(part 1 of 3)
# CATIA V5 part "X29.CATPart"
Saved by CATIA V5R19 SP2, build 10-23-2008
Part number: X-29
Material "Bronze": density 8860 kg/m3, Young's modulus 1.1e+11 Pa, Poisson ratio 0.341, thermal expansion 1.78e-05 1/K
Material "Bronze": density 8860 kg/m3, Young's modulus 1.1e+11 Pa, Poisson ratio 0.341, thermal expansion 1.78e-05 1/K
Material "White": density 7860 kg/m3, Young's modulus 2e+11 Pa, Poisson ratio 0.266
Material "White": density 7860 kg/m3, Young's modulus 2e+11 Pa, Poisson ratio 0.266
Bounding box of the stored display mesh (mm): x -1455.5 to 274.22, y -414.245 to 414.245, z -32.245 to 318.784
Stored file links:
  C:\Users\Pablo\Desktop\Cati XPM\X 29\X29.CATPart
  C:\Program Files\CATIA V19\intel_a\startup\materials\Catalog.CATMaterial
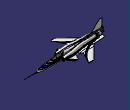
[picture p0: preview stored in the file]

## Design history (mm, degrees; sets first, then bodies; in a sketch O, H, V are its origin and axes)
Set1
  Sketch1 "SIZE CALIBRATE 1 IN 10" on xy-plane, origin (0, 0, 0), H (1, 0, 0), V (0, 1, 0)
    line L1 (-281.9, -45.8) -> (18.1, -45.8)
    point P2 (18.1, -45.8)
    line L2 (-41.1, -46) -> (18.1, -46)
    length L1 = 300
    length L2 = 59.2
    horizontal: L1 H, L2 H
    fix: P2
  Sketch2 "CALIB2" on xy-plane, origin (0, 0, 0), H (1, 0, 0), V (0, 1, 0)
    line L1 (-816.9, 412.5) -> (-816.9, -414.5)
    length L1 = 827
    vertical: L1 V
  Sketch3 "CALIB3" on yz-plane, origin (0, 0, 0), H (0, 1, 0), V (0, 0, 1)
    line L1 (-473.1, 37.9) -> (465.3, 37.9)
    point P2 (465.3, 37.9)
    projected line E1 (412.5, 0) -> (-414.5, 0) from Sketch2.L1
    length L1 = 938.4
    length E1 = 827 (reference)
    horizontal: L1 H
    fix: P2
  Sketch4 on zx-plane, origin (0, 0, 0), H (-1, 0, 0), V (0, 0, 1)
    line L1 (0, 0) -> (267.3, 0)
    line L2 (267.3, 0) -> (267.3, 23.6274)
    length L1 = 267.3
    horizontal: L1 H
    vertical: L2 V
  Sketch5 on xy-plane, origin (0, 0, 0), H (1, 0, 0), V (0, 1, 0)
    line L1 (0, 0) -> (-1457.6, 0)
    length L1 = 1457.6
    horizontal: L1 H
  St3DCurveFeature1 "CATSt3DCurveFeatureName": Order 6, CreationType 2, ClosureMode false, ConstructionPoints ({point type Coord, X -1.9383, Y 5.9343, Z 0}; {point type Coord, X -24.2902, Y 15.8221, Z 0}; {point type Coord, X -62.5655, Y 28.9818, Z 0}; {point type Coord, X -118.7401, Y 40.764, Z 0}; {point type Coord, X -165.694, Y 45.9382, Z 0}; {point type Coord, X -206.5921, Y 48.6971, Z 0}; {point type Coord, X -259.8651, Y 50.5364, Z 0}; {point type Coord, X -315.1978, Y 50.8218, Z 0}; {point type Coord, X -357.1922, Y 50.4817, Z 0}; {point type Coord, X -448.0335, Y 49.8551, Z 0}; {point type Coord, X -538.2728, Y 48.6416, Z 0}; {point type Coord, X -621.671, Y 48.6264, Z 0}; {point type Coord, X -667.4203, Y 47.391, Z 0}; {point type Coord, X -684.8796, Y 46.6781, Z 0}; {point type Coord, X -722.2255, Y 43.9186, Z 0}; {point type Coord, X -762.4405, Y 39.603, Z 0}; {point type Coord, X -787.4084, Y 36.6575, Z 0}; {point type Coord, X -818.1768, Y 33.1426, Z 0}), SymmetryMode false
  St3DCurveFeature2 "CATSt3DCurveFeatureName": Order 6, CreationType 2, ClosureMode false, ConstructionPoints ({point type Coord, X -507.4834, Y 97.0494, Z 0}; {point type Coord, X -530.8481, Y 96.9821, Z 0}; {point type Coord, X -587.9066, Y 97.5878, Z -3.7019}; {point type Coord, X -647.6501, Y 98.1847, Z -9.8719}; {point type Coord, X -697.045, Y 95.7458, Z -18.0162}; {point type Coord, X -747.9643, Y 90.6206, Z -22.9521}; {point type Coord, X -774.7582, Y 85.9469, Z -23.4457}; {point type Coord, X -803.8511, Y 81.6498, Z -24.4677}; {point type Coord, X -823.754, Y 77.7619, Z -24.6797}; {point type Coord, X -849.4023, Y 73.0846, Z -24.6424}; {point type Coord, X -882.7974, Y 68.7832, Z -24.5746}; {point type Coord, X -942.1395, Y 64.0162, Z -24.58}; {point type Coord, X -1018.7672, Y 60.7338, Z -19.3219}; {point type Coord, X -1067.7792, Y 58.296, Z -14.7664}; {point type Coord, X -1138.3186, Y 55.0309, Z -8.0901}; {point type Coord, X -1205.3285, Y 52.1589, Z -2.5716}; {point type Coord, X -1313.7551, Y 46.8707, Z 7.2925}), SymmetryMode false
  St3DCurveFeature3 "CATSt3DCurveFeatureName": Order 6, CreationType 2, ClosureMode false, ConstructionPoints ({point type Coord, X -525.9838, Y 55.3979, Z 0}; {point type Coord, X -543.2538, Y 55.9968, Z 0}; {point type Coord, X -574.5548, Y 56.772, Z 0}; {point type Coord, X -628.0893, Y 57.7, Z 0}; {point type Coord, X -661.1129, Y 56.9586, Z 0}; {point type Coord, X -721.9703, Y 52.2509, Z 0}; {point type Coord, X -755.0441, Y 48.0325, Z 0}; {point type Coord, X -785.2518, Y 44.2786, Z 0}; {point type Coord, X -818.4777, Y 38.7854, Z 0}), SymmetryMode false
  St3DCurveFeature4 "CATSt3DCurveFeatureName": Order 6, CreationType 2, ClosureMode false, ConstructionPoints ({point type OnCurve, Support St3DCurveFeature5, Real 0.228358}; {point type Coord, X -314.3415, Y 1.8332, Z 75.4181}; {point type Coord, X -316.8842, Y 7.3821, Z 75.2006}; {point type Coord, X -319.6261, Y 11.0741, Z 74.9841}; {point type Coord, X -323.9821, Y 15.3852, Z 74.6245}; {point type Coord, X -327.4218, Y 18.0789, Z 74.3128}; {point type Coord, X -331.264, Y 20.7701, Z 73.9983}; {point type Coord, X -336.765, Y 24.0359, Z 73.5381}; {point type Coord, X -343.657, Y 27.3619, Z 72.9256}; {point type Coord, X -355.1724, Y 31.6887, Z 72.4729}; {point type Coord, X -370.8877, Y 36.3523, Z 72.1927}; {point type Coord, X -383.7912, Y 38.4954, Z 72.1897}; {point type Coord, X -397.3184, Y 39.8515, Z 72.0898}; {point type Coord, X -410.2175, Y 40.3042, Z 72.0663}; {point type Coord, X -425.4017, Y 40.2956, Z 71.9107}; {point type Coord, X -445.88, Y 40.0632, Z 72.8633}; {point type Coord, X -475.1823, Y 39.9786, Z 73.1473}; {point type Coord, X -502.6331, Y 40.1639, Z 74.0639}; {point type Coord, X -535.3124, Y 39.986, Z 75.7138}; {point type Coord, X -568.9066, Y 40.0706, Z 80.0391}; {point type Coord, X -609.7247, Y 39.4157, Z 85.4714}; {point type Coord, X -649.066, Y 38.9447, Z 89.9952}; {point type Coord, X -688.7982, Y 37.2164, Z 93.6057}; {point type Coord, X -718.2576, Y 35.6931, Z 96.5137}; {point type Coord, X -745.7382, Y 33.8178, Z 98.8225}; {point type Coord, X -777.5668, Y 30.4924, Z 101.3612}; {point type Coord, X -811.1523, Y 27.5214, Z 104.1194}; {point type Coord, X -849.8104, Y 23.8172, Z 106.5843}; {point type Coord, X -883.9333, Y 20.3055, Z 108.4864}; {point type Coord, X -923.3079, Y 16.9587, Z 111.2445}; {point type Coord, X -963.1815, Y 14.1496, Z 113.0833}; {point type Coord, X -989.4026, Y 11.559, Z 113.0833}), SymmetryMode false
  St3DCurveFeature5 "TOP KINGPOST": Order 6, CreationType 2, ClosureMode false, ConstructionPoints ({point type Coord, X -1.3908, Y 0, Z 4.8279}; {point type Coord, X -8.4225, Y 0, Z 8.3879}; {point type Coord, X -18.6736, Y 0, Z 12.2022}; {point type Coord, X -36.3801, Y 0, Z 17.6269}; {point type Coord, X -51.7991, Y 0, Z 21.9498}; {point type Coord, X -79.871, Y 0, Z 28.6853}; {point type Coord, X -121.7227, Y 0, Z 37.5338}; {point type Coord, X -165.4722, Y 0, Z 46.0493}; {point type Coord, X -214.3044, Y 0, Z 55.3335}; {point type Coord, X -249.384, Y 0, Z 62.278}; {point type Coord, X -279.7975, Y 0, Z 68.5356}; {point type Coord, X -300.5133, Y 0, Z 72.3905}; {point type Coord, X -307.3014, Y 0, Z 73.7945}; {point type Coord, X -311.8016, Y 0, Z 74.8572}; {point type Coord, X -319.3684, Y 0, Z 77.0991}; {point type Coord, X -326.8112, Y 0, Z 79.8683}; {point type Coord, X -345.5423, Y 0, Z 87.9274}; {point type Coord, X -373.9217, Y 0, Z 99.7273}; {point type Coord, X -398.4795, Y 0, Z 110.3991}; {point type Coord, X -427.8123, Y 0, Z 119.7208}; {point type Coord, X -447.7116, Y 0, Z 123.739}; {point type Coord, X -479.5777, Y 0, Z 126.928}; {point type Coord, X -505.6023, Y 0, Z 127.7406}; {point type Coord, X -529.4686, Y 0, Z 127.207}; {point type Coord, X -566.5783, Y 0, Z 124.5391}; {point type Coord, X -585.378, Y 0, Z 122.4048}; {point type Coord, X -609.813, Y 0, Z 120.445}; {point type Coord, X -632.0792, Y 0, Z 119.1111}; {point type Coord, X -659.1454, Y 0, Z 118.4441}; {point type Coord, X -695.947, Y 0, Z 117.5944}; {point type Coord, X -729.46, Y 0, Z 116.9379}; {point type Coord, X -761.9421, Y 0, Z 116.2814}; {point type Coord, X -806.6111, Y 0, Z 115.2966}; {point type Coord, X -849.2643, Y 0, Z 115.4607}; {point type Coord, X -918.1919, Y 0, Z 115.2966}; {point type Coord, X -957.8922, Y 0, Z 114.8042}; {point type Coord, X -995.5156, Y 0, Z 114.476}; {point type Coord, X -1029.6381, Y 0, Z 114.6401}; {point type Coord, X -1086.9321, Y 0, Z 114.9684}; {point type Coord, X -1152.2244, Y 0, Z 115.1325}; {point type Coord, X -1232.1786, Y 0, Z 116.1173}; {point type Coord, X -1274.5441, Y 0, Z 115.7891}; {point type Coord, X -1304.0731, Y 0, Z 115.2967}; {point type Coord, X -1340.9845, Y 0, Z 112.9988}; {point type Coord, X -1361.3268, Y 0, Z 109.8803}; {point type Coord, X -1388.5592, Y 0, Z 105.777}), SymmetryMode false
  Line1: type PtDir, RefPoint vertex of St3DCurveFeature5, Direction xy-plane, Start 0, End -11
  St3DCurveFeature6 "HIDDEN KEEL": Order 6, CreationType 2, ClosureMode false, ConstructionPoints ({point type OnCurve, Support Line1, Real 0}; {point type Coord, X -8.1577, Y 0, Z -8.9268}; {point type Coord, X -16.8086, Y 0, Z -11.6761}; {point type Coord, X -32.7873, Y 0, Z -15.6372}; {point type Coord, X -54.4858, Y 0, Z -19.7845}; {point type Coord, X -80.8456, Y 0, Z -22.7321}; {point type Coord, X -117.4146, Y 0, Z -25.5885}; {point type Coord, X -152.4678, Y 0, Z -27.9816}; {point type Coord, X -207.8014, Y 0, Z -29.893}; {point type Coord, X -286.132, Y 0, Z -30.3156}; {point type Coord, X -356.7514, Y 0, Z -29.0986}; {point type Coord, X -430.7348, Y 0, Z -28.2478}; {point type Coord, X -530.0544, Y 0, Z -25.4118}; {point type Coord, X -600.3528, Y 0, Z -23.4266}; {point type Coord, X -625.014, Y 0, Z -23.143}; {point type Coord, X -675.559, Y 0, Z -23.143}; {point type Coord, X -730.5505, Y 0, Z -22.5758}; {point type Coord, X -809.2719, Y 0, Z -24.5014}; {point type Coord, X -870.6227, Y 0, Z -24.5014}; {point type Coord, X -944.4781, Y 0, Z -24.5014}; {point type Coord, X -1018.3336, Y 0, Z -19.4189}; {point type Coord, X -1107.142, Y 0, Z -10.8177}; {point type Coord, X -1200.5359, Y 0, Z -2.9985}; {point type Coord, X -1266.5759, Y 0, Z 2.475}; {point type Coord, X -1343.2783, Y 0, Z 11.0762}; {point type Coord, X -1390.9523, Y 0, Z 18.5044}), SymmetryMode false
  Point1: type OnPlane, Support xy-plane, H -867.63, V 161.579, Direction (1, 0, 0)
  Point2: type OnPlane, Support xy-plane, H -727.116, V 412.471, Direction (1, 0, 0)
  Point3: type OnPlane, Support xy-plane, H -845, V 412.72, Direction (1, 0, 0)
  Point4: type OnPlane, Support xy-plane, H -1140.324, V 114.749, Direction (1, 0, 0)
  Point5: type OnPlane, Support xy-plane, H -1394.714, V 110.442, Direction (1, 0, 0)
  Point6: type OnPlane, Support xy-plane, H -1392.885, V 51.929, Direction (1, 0, 0)
  Point7: type OnCurve, Support St3DCurveFeature2, Length 312.932
  Point8: type OnPlane, Support xy-plane, H -893.444, V 161.055, Direction (1, 0, 0)
  Point9: type OnCurve, Support St3DCurveFeature2, Length 388.312
  Plane1: type OffsetPt, RefPlane zx-plane, RefPoint vertex of St3DCurveFeature2
  Sketch6 on Plane1, origin (0, 97.0494, 0), H (-1, 0, 0), V (0, 0, 1)
    point P1 (507.4834, 0)
    reference projected point E1 (507.4834, 0) from vertex of St3DCurveFeature2
    construction line L1 (509.2, 68.5) -> (517.8, 6.5)
    line L2 (512.3122, -34.8124) -> (503.7889, 26.6343)
    coincidence: P1 E1, L2 P1
    fix: L1
    parallelism: L2 L1
  St3DCurveFeature7 "CATSt3DCurveFeatureName": Order 6, CreationType 2, ClosureMode false, ConstructionPoints ({point type Coord, X -545.6321, Y 104.119, Z 11.0414}; {point type Coord, X -642.6498, Y 208.7685, Z 3.33}), SymmetryMode false
  St3DCurveFeature8 "CATSt3DCurveFeatureName": Order 6, CreationType 2, ClosureMode false, ConstructionPoints ({point type Coord, X -708.7941, Y 208.8079, Z 4.1135}; {point type Coord, X -761.6417, Y 105.471, Z 7.1444}), SymmetryMode false
  St3DCurveFeature9 "CATSt3DCurveFeatureName": Order 6, CreationType 2, ClosureMode false, ConstructionPoints ({point type OnCurve, Support St3DCurveFeature7, Real 1}; {point type Coord, X -648.2798, Y 208.7184, Z 4.7164}; {point type Coord, X -652.9392, Y 208.7055, Z 5.5009}; {point type Coord, X -659.2364, Y 208.6877, Z 6.1713}; {point type Coord, X -667.9556, Y 208.663, Z 6.3894}; {point type Coord, X -678.2494, Y 208.7549, Z 6.1826}; {point type Coord, X -689.7546, Y 208.6008, Z 5.6234}; {point type Coord, X -700.1691, Y 208.6925, Z 4.8312}; {point type OnCurve, Support St3DCurveFeature8, Real 0}), SymmetryMode false
  St3DCurveFeature10 "CATSt3DCurveFeatureName": Order 6, CreationType 2, ClosureMode false, ConstructionPoints ({point type OnCurve, Support St3DCurveFeature7, Real 0}; {point type Coord, X -561.1128, Y 104.119, Z 14.124}; {point type Coord, X -581.8692, Y 104.119, Z 15.6509}; {point type Coord, X -609.3409, Y 104.119, Z 15.9563}; {point type Coord, X -656.9584, Y 104.119, Z 15.3455}; {point type Coord, X -684.1249, Y 104.119, Z 14.124}; {point type Coord, X -732.6582, Y 104.119, Z 10.7647}; {point type OnCurve, Support St3DCurveFeature8, Real 1}), SymmetryMode false
  Loft1 "RUDDER WING TOP": Sections (St3DCurveFeature10; St3DCurveFeature9), Guides (St3DCurveFeature7; St3DCurveFeature8)
  Plane2: type 3Points, Element1 vertex of St3DCurveFeature7, Element2 vertex of St3DCurveFeature8, Element3 vertex of St3DCurveFeature8
  Symmetry1: ToTransfor St3DCurveFeature9, Reference Plane2
  St3DCurveFeature11 "CATSt3DCurveFeatureName": Order 6, CreationType 2, ClosureMode false, ConstructionPoints ({point type OnCurve, Support St3DCurveFeature7, Real 0}; {point type Coord, X -557.7115, Y 104.119, Z 6.8476}; {point type Coord, X -582.5415, Y 104.119, Z 3.1991}; {point type Coord, X -597.3988, Y 104.119, Z 1.8923}; {point type Coord, X -625.4462, Y 104.119, Z 0.0858}; {point type Coord, X -649.0419, Y 104.119, Z 0.0304}; {point type Coord, X -707.4041, Y 104.119, Z 2.9244}; {point type OnCurve, Support St3DCurveFeature8, Real 1}), SymmetryMode false
  Loft2 "RUDDER WING BOTTOM": Sections (St3DCurveFeature11; Symmetry1), Guides (St3DCurveFeature7; St3DCurveFeature8)
  Fill1 "RUDDER WING END": Boundary (St3DCurveFeature9; Symmetry1)
  MultiSel1
  Sketch7 "CROSS SECTIONS1" on xy-plane, origin (0, 0, 0), H (1, 0, 0), V (0, 1, 0)
    line L1 (-68.7, 51.8) -> (-68.7, -69.3)
    line L2 (-189.3, 68.1) -> (-189.3, -89.9)
    line L3 (-7.8, 68.1) -> (-7.8, -73.6)
    line L4 (-411.7, 99) -> (-411.7, -113.5)
    line L5 (-729.9, 209.7948) -> (-729.9, -276.0052)
    line L6 (-893.1, 253.0256) -> (-893.1, -357.5744)
    line L7 (-989.5, 282.1874) -> (-989.5, -392.7781)
    line L8 (-45.259, 11.8) -> (-213.359, 11.8)
    line L9 (-167.5393, 17.2) -> (-333.1393, 17.2)
    line L10 (-347.9221, 122.8124) -> (-347.9221, -113.5105)
    line L11 (-485.7, 138.9) -> (-485.7, -145.7)
    line L12 (-287.1, 113.4608) -> (-287.1, -113.571)
    line L13 (-818.2, 104.7032) -> (-818.2, -72.5968)
    line L14 (-1314.9, 45.4) -> (-1314.9, -53.6)
    line L15 (-1396.2, 40.7) -> (-1396.2, -3.85)
    point P30 (-1396.2, -48.4)
    line L16 (-1396.2, -3.85) -> (-1416.7, -3.85)
    line L17 (-1060.6, 142.1) -> (-1060.6, -115.6)
    line L18 (-1149.8, 137.1) -> (-1149.8, -149.9)
    line L19 (-1252.4, 134.2613) -> (-1252.4, -166.6387)
    line L20 (-1292.2, 134.2613) -> (-1292.2, -173)
    vertical: L1 V, L2 V, L3 V, L4 V, L5 V, L6 V, L10 V, L7 V, L11 V, L12 V, L13 V, L14 V, L15 V, L17 V, L18 V, L19 V, L20 V
    horizontal: L8 H, L9 H, L16 H
  St3DCurveFeature12 "CATSt3DCurveFeatureName": Order 6, CreationType 2, ClosureMode false, ConstructionPoints ({point type OnCurve, Support St3DCurveFeature1, Real 0.0866401}; {point type Coord, X -68.7112, Y 21.24, Z 21.2489}; {point type Coord, X -68.716, Y 10.9917, Z 25.3331}; {point type OnCurve, Support St3DCurveFeature5, Real 0.050363}; {point type Coord, X -68.7168, Y -9.2145, Z 25.6576}; {point type Coord, X -68.7103, Y -22.6195, Z 19.6052}; {point type OnCurve, Support {symmetry ToTransfor St3DCurveFeature1, Reference zx-plane}, Real 0.0866315}), SymmetryMode false
  St3DCurveFeature13 "CATSt3DCurveFeatureName": Order 6, CreationType 2, ClosureMode false, ConstructionPoints ({point type OnCurve, Support St3DCurveFeature1, Real 0.234866}; {point type Coord, X -189.2963, Y 27.3945, Z 44.351}; {point type Coord, X -189.2967, Y 13.0311, Z 49.7509}; {point type OnCurve, Support St3DCurveFeature5, Real 0.137895}; {point type Coord, X -189.2979, Y -16.1207, Z 49.0781}; {point type Coord, X -189.2996, Y -35.7618, Z 39.1738}; {point type OnCurve, Support {symmetry ToTransfor St3DCurveFeature1, Reference zx-plane}, Real 0.234869}), SymmetryMode false
  Point10: (0, 0, 0), relative to {intersect ToIntersect1 St3DCurveFeature5, ToIntersect2 St3DCurveFeature12}
  Split1: ToCut St3DCurveFeature12, Cutting Point10
  Symmetry2: ToTransfor Split1, Reference zx-plane
  Join1 "SECOND SECTION TOP": Elements (Split1; Symmetry2)
  St3DCurveFeature14 "CATSt3DCurveFeatureName": Order 6, CreationType 2, ClosureMode false, ConstructionPoints ({point type OnCurve, Support St3DCurveFeature1, Real 0}; {point type Coord, X -1.5651, Y 4.2929, Z 3.4828}; {point type OnCurve, Support St3DCurveFeature5, Real 0}), SymmetryMode false
  Symmetry3: ToTransfor St3DCurveFeature14, Reference zx-plane
  Join2 "FIRST SECTION TOP": Elements (St3DCurveFeature14; Symmetry3)
  Point11: (0, 0, 0), relative to {intersect ToIntersect1 St3DCurveFeature13, ToIntersect2 St3DCurveFeature5}
  Split2: ToCut St3DCurveFeature13, Cutting Point11
  Symmetry4: ToTransfor Split2, Reference zx-plane
  Join3 "3RD SECTION TOP": Elements (Split2; Symmetry4)
  St3DCurveFeature15 "CATSt3DCurveFeatureName": Order 6, CreationType 2, ClosureMode false, ConstructionPoints ({point type OnCurve, Support St3DCurveFeature1, Real 0.353806}; {point type Coord, X -287.1183, Y 35.4417, Z 49.2979}; {point type Coord, X -287.1172, Y 9.8004, Z 68.6527}; {point type OnCurve, Support St3DCurveFeature5, Real 0.208828}), SymmetryMode false
  St3DCurveFeature16 "CATSt3DCurveFeatureName": Order 6, CreationType 2, ClosureMode false, ConstructionPoints ({point type OnCurve, Support St3DCurveFeature1, Real 0.427791}; {point type Coord, X -347.8776, Y 43.2741, Z 42.8905}; {point type Coord, X -347.8936, Y 34.678, Z 63.3624}; {point type OnCurve, Support St3DCurveFeature4, Real 0.0671855}; {point type Coord, X -347.9386, Y 20.8259, Z 82.0095}; {point type Coord, X -347.9801, Y 9.5891, Z 87.8724}; {point type OnCurve, Support St3DCurveFeature5, Real 0.254433}), SymmetryMode false
  St3DCurveFeature17 "CATSt3DCurveFeatureName": Order 6, CreationType 2, ClosureMode false, ConstructionPoints ({point type OnCurve, Support St3DCurveFeature1, Real 0.505163}; {point type Coord, X -411.7253, Y 49.0015, Z 39.9798}; {point type Coord, X -411.7264, Y 43.1268, Z 64.6744}; {point type OnCurve, Support St3DCurveFeature4, Real 0.16137}; {point type Coord, X -411.7184, Y 33.4767, Z 91.2015}; {point type Coord, X -411.7046, Y 14.2813, Z 112.2051}; {point type OnCurve, Support St3DCurveFeature5, Real 0.303426}), SymmetryMode false
  St3DCurveFeature18 "CATSt3DCurveFeatureName": Order 6, CreationType 2, ClosureMode false, ConstructionPoints ({point type OnCurve, Support St3DCurveFeature1, Real 0.595096}; {point type Coord, X -485.719, Y 44.7736, Z 59.8509}; {point type Coord, X -485.7206, Y 42.4715, Z 66.9884}; {point type OnCurve, Support St3DCurveFeature4, Real 0.268273}; {point type Coord, X -485.718, Y 37.5245, Z 90.9449}; {point type Coord, X -485.7052, Y 10.2998, Z 125.6335}; {point type OnCurve, Support St3DCurveFeature5, Real 0.356943}), SymmetryMode false
  St3DCurveFeature19 "CATSt3DCurveFeatureName": Order 6, CreationType 2, ClosureMode false, ConstructionPoints ({point type OnCurve, Support St3DCurveFeature1, Real 0.892179}; {point type Coord, X -729.8675, Y 38.7337, Z 87.4092}; {point type Coord, X -729.8719, Y 36.6611, Z 93.7617}; {point type OnCurve, Support St3DCurveFeature4, Real 0.622894}; {point type Coord, X -729.8953, Y 23.3563, Z 110.5578}; {point type Coord, X -729.9281, Y 5.3961, Z 116.2674}; {point type OnCurve, Support St3DCurveFeature5, Real 0.530974}), SymmetryMode false
  St3DCurveFeature20 "CATSt3DCurveFeatureName": Order 6, CreationType 2, ClosureMode false, ConstructionPoints ({point type OnCurve, Support St3DCurveFeature1, Real 1}; {point type Coord, X -818.1839, Y 32.6382, Z 93.3647}; {point type Coord, X -818.184, Y 28.4308, Z 102.5145}; {point type OnCurve, Support St3DCurveFeature4, Real 0.75137}; {point type Coord, X -818.1841, Y 16.9143, Z 111.7131}; {point type Coord, X -818.184, Y 6.0236, Z 114.5638}; {point type OnCurve, Support St3DCurveFeature5, Real 0.593764}), SymmetryMode false
  MultiSel2
  Join4 "4TH SECTION TOP": Elements (St3DCurveFeature15; {symmetry ToTransfor St3DCurveFeature15, Reference zx-plane})
  Join5 "5TH SECTION TOP": Elements (St3DCurveFeature16; {symmetry ToTransfor St3DCurveFeature16, Reference zx-plane})
  Join6 "6 SECTION TOP": Elements (St3DCurveFeature17; {symmetry ToTransfor St3DCurveFeature17, Reference zx-plane})
  MultiSel3
  Join7 "7 SECTION TOP": Elements (St3DCurveFeature18; {symmetry ToTransfor St3DCurveFeature18, Reference zx-plane})
  Join8 "8 SECTION TOP": Elements (St3DCurveFeature19; {symmetry ToTransfor St3DCurveFeature19, Reference zx-plane})
  Join9 "9 SECTION TOP": Elements (St3DCurveFeature20; {symmetry ToTransfor St3DCurveFeature20, Reference zx-plane})
  Loft3 "YES IT IS AWESOME TOP": Sections (Join2; Join1; Join3; Join4; Join5; Join6; Join7; Join8; Join9), Guides (St3DCurveFeature1; {symmetry ToTransfor St3DCurveFeature1, Reference zx-plane}; St3DCurveFeature5)
  MultiSel4 "RUDDER WING MIRROR"
  St3DCurveFeature21 "CATSt3DCurveFeatureName": Order 6, CreationType 2, ClosureMode false, ConstructionPoints ({point type OnCurve, Support St3DCurveFeature1, Real 0}; {point type Coord, X -1.7649, Y 4.4103, Z -4.2934}; {point type Coord, X -1.5379, Y 1.5948, Z -6.0197}; {point type OnCurve, Support St3DCurveFeature6, Real 0}), SymmetryMode false
  St3DCurveFeature22 "CATSt3DCurveFeatureName": Order 6, CreationType 2, ClosureMode false, ConstructionPoints ({point type OnCurve, Support St3DCurveFeature1, Real 0.00790303}; {point type Coord, X -7.8235, Y 7.0564, Z -5.6144}; {point type Coord, X -7.8237, Y 4.919, Z -7.6407}; {point type OnCurve, Support St3DCurveFeature6, Real 0.00498706}), SymmetryMode false
  St3DCurveFeature23 "CATSt3DCurveFeatureName": Order 6, CreationType 2, ClosureMode false, ConstructionPoints ({point type OnCurve, Support St3DCurveFeature6, Real 0.0496908}; {point type Coord, X -68.7003, Y 7.6425, Z -21.3907}; {point type Coord, X -68.7024, Y 20.1879, Z -18.641}; {point type OnCurve, Support St3DCurveFeature1, Real 0.0866432}), SymmetryMode false
  St3DCurveFeature24 "CATSt3DCurveFeatureName": Order 6, CreationType 2, ClosureMode false, ConstructionPoints ({point type OnCurve, Support St3DCurveFeature1, Real 0.234931}; {point type Coord, X -189.3345, Y 35.9009, Z -23.3193}; {point type Coord, X -189.3195, Y 19.9451, Z -28.2949}; {point type OnCurve, Support St3DCurveFeature6, Real 0.136395}), SymmetryMode false
  St3DCurveFeature25 "CATSt3DCurveFeatureName": Order 6, CreationType 2, ClosureMode false, ConstructionPoints ({point type OnCurve, Support St3DCurveFeature1, Real 0.427682}; {point type Coord, X -347.9196, Y 41.2804, Z -23.4978}; {point type Coord, X -347.9213, Y 11.6906, Z -28.8573}; {point type OnCurve, Support St3DCurveFeature6, Real 0.250183}), SymmetryMode false
  St3DCurveFeature26 "CATSt3DCurveFeatureName": Order 6, CreationType 2, ClosureMode false, ConstructionPoints ({point type OnCurve, Support St3DCurveFeature1, Real 0.595119}; {point type Coord, X -485.7032, Y 39.5663, Z -22.4192}; {point type Coord, X -485.6997, Y 8.8378, Z -26.7197}; {point type OnCurve, Support St3DCurveFeature6, Real 0.349026}), SymmetryMode false
  St3DCurveFeature27 "CATSt3DCurveFeatureName": Order 6, CreationType 2, ClosureMode false, ConstructionPoints ({point type OnCurve, Support St3DCurveFeature1, Real 0.892143}; {point type Coord, X -729.9478, Y 35.0989, Z -18.7025}; {point type Coord, X -729.8962, Y 11.0518, Z -22.5341}; {point type OnCurve, Support St3DCurveFeature6, Real 0.524202}), SymmetryMode false
  St3DCurveFeature28 "CATSt3DCurveFeatureName": Order 6, CreationType 2, ClosureMode false, ConstructionPoints ({point type OnCurve, Support St3DCurveFeature1, Real 1}; {point type Coord, X -818.2306, Y 22.8732, Z -21.3068}; {point type Coord, X -818.2837, Y 9.7845, Z -24.3328}; {point type OnCurve, Support St3DCurveFeature6, Real 0.587671}), SymmetryMode false
  MultiSel5
  Join10 "1 S BOTTOM": Elements (St3DCurveFeature21; {symmetry ToTransfor St3DCurveFeature21, Reference zx-plane})
  Join11 "2 S BOTTOM": Elements (St3DCurveFeature22; {symmetry ToTransfor St3DCurveFeature22, Reference zx-plane})
  Join12 "3 S BOTTOM": Elements (St3DCurveFeature23; {symmetry ToTransfor St3DCurveFeature23, Reference zx-plane})
  Join13 "4 S BOTTOM": Elements (St3DCurveFeature24; {symmetry ToTransfor St3DCurveFeature24, Reference zx-plane})
  Join14 "5 S BOTTOM": Elements (St3DCurveFeature25; {symmetry ToTransfor St3DCurveFeature25, Reference zx-plane})
  Join15 "6 S BOTTOM": Elements (St3DCurveFeature26; {symmetry ToTransfor St3DCurveFeature26, Reference zx-plane})
  Join16 "7 S BOTTOM": Elements (St3DCurveFeature27; {symmetry ToTransfor St3DCurveFeature27, Reference zx-plane})
  Join17 "9 S BOTTOM": Elements (St3DCurveFeature28; {symmetry ToTransfor St3DCurveFeature28, Reference zx-plane})
  Loft4 "YES IT IS AWESOME BOTTOM": Sections (Join10; Join11; Join12; Join13; Join14; Join15; Join16; Join17), Guides (St3DCurveFeature1; St3DCurveFeature6; {symmetry ToTransfor St3DCurveFeature1, Reference zx-plane})
  St3DCurveFeature29 "CATSt3DCurveFeatureName": Order 6, CreationType 2, ClosureMode false, ConstructionPoints ({point type Coord, X -504.7918, Y 62.7154, Z 68.5947}; {point type Coord, X -512.2895, Y 62.5633, Z 70.2887}; {point type Coord, X -531.3045, Y 62.3962, Z 73.2638}; {point type Coord, X -559.375, Y 62.4299, Z 77.9126}; {point type Coord, X -585.9734, Y 62.2412, Z 81.8175}; {point type Coord, X -638.5564, Y 61.7736, Z 88.6976}; {point type Coord, X -688.8547, Y 59.8651, Z 93.438}; {point type Coord, X -741.086, Y 54.9491, Z 98.5529}; {point type Coord, X -831.316, Y 42.1554, Z 105.3623}; {point type Coord, X -856.3709, Y 39.0823, Z 107.0172}; {point type Coord, X -906.88, Y 33.4648, Z 109.1478}; {point type Coord, X -974.2931, Y 30.6249, Z 112.3131}; {point type Coord, X -1027.2833, Y 30.6513, Z 113.2555}; {point type Coord, X -1209.5607, Y 33.6414, Z 116.2408}; {point type Coord, X -1313.864, Y 33.3458, Z 113.6748}), SymmetryMode false
  St3DCurveFeature30 "CATSt3DCurveFeatureName": Order 6, CreationType 2, ClosureMode false, ConstructionPoints ({point type Coord, X -507.4834, Y 97.0494, Z 69.2356}; {point type Coord, X -530.8481, Y 96.9821, Z 73.1593}; {point type Coord, X -587.9066, Y 97.5878, Z 82.6011}; {point type Coord, X -647.6501, Y 98.1847, Z 89.6382}; {point type Coord, X -697.045, Y 95.7458, Z 94.3704}; {point type Coord, X -747.9643, Y 90.6206, Z 99.0448}; {point type Coord, X -774.7582, Y 85.9469, Z 101.2173}; {point type Coord, X -803.8511, Y 81.6498, Z 103.6837}; {point type Coord, X -823.754, Y 77.7619, Z 104.9405}; {point type Coord, X -849.4023, Y 73.0846, Z 106.8138}; {point type Coord, X -882.7974, Y 68.7832, Z 108.3504}; {point type Coord, X -942.1395, Y 64.0162, Z 110.7317}; {point type Coord, X -1018.7672, Y 60.7338, Z 113.0522}; {point type Coord, X -1067.7792, Y 58.296, Z 113.5685}; {point type Coord, X -1138.3186, Y 55.0309, Z 114.9205}; {point type Coord, X -1205.3285, Y 52.1589, Z 116.0327}; {point type Coord, X -1313.7551, Y 46.8707, Z 113.7793}), SymmetryMode false
  St3DCurveFeature31 "LOWER INTAKE CURVE": Order 6, CreationType 2, ClosureMode false, ConstructionPoints ({point type Coord, X -508.205, Y 62.7154, Z -0.0049}; {point type Coord, X -512.2895, Y 62.5633, Z -0.0266}; {point type Coord, X -531.3045, Y 62.3962, Z 0.0637}; {point type Coord, X -559.375, Y 62.4299, Z -1.5121}; {point type Coord, X -585.9734, Y 62.2412, Z -3.635}; {point type Coord, X -638.5564, Y 61.7736, Z -8.6802}; {point type Coord, X -688.8547, Y 59.8651, Z -16.7888}; {point type Coord, X -741.086, Y 54.9491, Z -22.478}; {point type Coord, X -831.316, Y 42.1554, Z -24.6143}; {point type Coord, X -856.3709, Y 39.0823, Z -25.0642}; {point type Coord, X -906.88, Y 33.4648, Z -24.5123}; {point type Coord, X -974.2931, Y 30.6249, Z -21.8907}; {point type Coord, X -1027.2833, Y 30.6513, Z -19.0312}; {point type Coord, X -1209.5607, Y 33.6414, Z -1.6668}; {point type Coord, X -1313.864, Y 33.3458, Z 8.2289}), SymmetryMode false
  St3DCurveFeature32 "CATSt3DCurveFeatureName": Order 6, CreationType 2, ClosureMode false, ConstructionPoints ({point type OnCurve, Support St3DCurveFeature29, Real 0}; {point type Coord, X -504.8914, Y 64.6271, Z 69.9562}; {point type Coord, X -507.3401, Y 94.6112, Z 70.9961}; {point type OnCurve, Support St3DCurveFeature30, Real 0}; {point type Coord, X -507.6079, Y 98.6621, Z 66.7623}; {point type Coord, X -507.7727, Y 100.7744, Z 59.8649}; {point type Coord, X -507.4941, Y 97.9118, Z 1.1978}; {point type OnCurve, Support St3DCurveFeature2, Real 0}; {point type Coord, X -507.4742, Y 93.1964, Z -3.262}; {point type Coord, X -507.7011, Y 87.5703, Z -5.3977}; {point type Coord, X -507.9546, Y 77.8875, Z -6.3524}; {point type Coord, X -508.2324, Y 64.7028, Z -3.4713}; {point type OnCurve, Support St3DCurveFeature31, Real 0}), SymmetryMode false
  St3DCurveFeature33 "CATSt3DCurveFeatureName": Order 6, CreationType 2, ClosureMode false, ConstructionPoints ({point type OnCurve, Support St3DCurveFeature29, Real 1}; {point type Coord, X -1313.8341, Y 34.7589, Z 114.0982}; {point type Coord, X -1313.7861, Y 45.031, Z 114.1435}; {point type OnCurve, Support St3DCurveFeature30, Real 1}; {point type Coord, X -1313.6199, Y 55.8095, Z 105.463}; {point type Coord, X -1313.5225, Y 57.528, Z 13.4237}; {point type Coord, X -1313.6126, Y 52.0017, Z 8.4722}; {point type OnCurve, Support St3DCurveFeature2, Real 1}; {point type Coord, X -1313.7745, Y 44.4705, Z 6.9938}; {point type Coord, X -1313.7941, Y 38.8159, Z 6.8078}; {point type Coord, X -1313.83, Y 34.8769, Z 7.3191}; {point type OnCurve, Support St3DCurveFeature31, Real 1}), SymmetryMode false
  St3DCurveFeature34 "CATSt3DCurveFeatureName": Order 6, CreationType 2, ClosureMode false, ConstructionPoints ({point type OnCurve, Support St3DCurveFeature29, Real 0.603521}; {point type Coord, X -991.4992, Y 32.3685, Z 113.4143}; {point type Coord, X -991.5243, Y 56.7287, Z 114.2619}; {point type OnCurve, Support St3DCurveFeature30, Real 0.602418}; {point type Coord, X -991.562, Y 65.1512, Z 107.0772}; {point type Coord, X -991.605, Y 71.7066, Z 73.6337}; {point type Coord, X -991.5638, Y 64.267, Z -19.1264}; {point type OnCurve, Support St3DCurveFeature2, Real 0.601069}; {point type Coord, X -991.5246, Y 58.2848, Z -24.0296}; {point type Coord, X -991.5118, Y 48.7103, Z -25.3475}; {point type Coord, X -991.4972, Y 32.5823, Z -23.1086}; {point type OnCurve, Support St3DCurveFeature31, Real 0.600418}), SymmetryMode false
  Loft5 "TURBINE INTAKE 1?": Sections (St3DCurveFeature32; St3DCurveFeature34; St3DCurveFeature33), Guides (St3DCurveFeature29; St3DCurveFeature30; St3DCurveFeature31)
  Symmetry5: ToTransfor Loft5, Reference zx-plane
  Plane3: type Offset, RefPlane zx-plane, Offset 291
  Sketch8 on Plane3, origin (0, 291, 0), H (-1, 0, 0), V (0, 0, 1)
    spline S1 through (821.2, -0.5) (824.3, -2.4) (838.4, -4.2) (841.7, -4.2) (922.1395, 0) (959.3395, 3.4071) (994.4395, 8.9071) (1023.8395, 13.7071) (1056.0395, 17.5071) (1145.7, 25.2) (1242.5395, 31.1071) (1386.3, 47.1)
    spline S2 through (821.2, -0.5) (821.9, 2) (828.3, 5.4) (835, 6.8) (851, 8.6) (878.3, 9.8) (922.6, 12.9) (1012.1, 22.4) (1126.9, 35.5) (1246.4, 41.6) (1386.3, 47.1)
    spline S3 through (734.9, 25.6) (746.5, 29.3) (754.7, 31) (767.9, 32.2) (780.1, 32.2) (806.5, 31) (821.9, 29.3) (832.6, 27.1) (853.4, 20.9)
    spline S4 through (734.9, 25.6) (736.2, 24.2) (739.5, 22.4) (744.1, 21.4) (754.2, 20.4) (770, 19.9) (794.5, 19.9) (820.2, 19.9) (853.4, 20.9)
    point P1 (922.1395, 0)
    point P2 (821.2, -0.5)
    point P3 (821.2, -0.5)
    point P4 (1386.3, 47.1)
    point P5 (1386.3, 47.1)
    point P6 (734.9, 25.6)
    point P7 (734.9, 25.6)
    point P8 (853.4, 20.9)
    point P9 (853.4, 20.9)
    coincidence: P1 H, P2 P3, P4 P5, P6 P7, P8 P9
    fix: P4, P2
  Sketch9 on xy-plane, origin (0, 0, 0), H (1, 0, 0), V (0, 1, 0)
    line L1 (-799.8221, 162.2) -> (-1172.0221, 162.2)
    line L2 (-1170.0241, 113.4) -> (-793.5241, 113.4)
    point P3 (-1170.0241, 113.4)
    line L3 (-959.764, 414.1) -> (-616.264, 414.1)
    horizontal: L1 H, L2 H, L3 H
  St3DCurveFeature35 "CATSt3DCurveFeatureName": Order 6, CreationType 2, ClosureMode false, ConstructionPoints ({point type Coord, X -867.4887, Y 161.7326, Z 17.1982}; {point type Coord, X -879.2042, Y 161.7551, Z 23.7617}; {point type Coord, X -892.0037, Y 161.7796, Z 27.5516}; {point type Coord, X -902.9147, Y 161.8006, Z 29.1274}; {point type Coord, X -914.2453, Y 161.8223, Z 29.3975}; {point type Coord, X -934.1788, Y 161.8606, Z 29.7132}; {point type Coord, X -984.7472, Y 161.9576, Z 29.3006}; {point type Coord, X -1009.5068, Y 162.0051, Z 29.7252}; {point type Coord, X -1033.2173, Y 162.0506, Z 29.8798}; {point type Coord, X -1059.8652, Y 162.1017, Z 29.5129}; {point type Coord, X -1094.3073, Y 162.1678, Z 26.1157}), SymmetryMode false
  St3DCurveFeature36 "CATSt3DCurveFeatureName": Order 6, CreationType 2, ClosureMode false, ConstructionPoints ({point type Coord, X -728.3605, Y 414.245, Z 24.1456}; {point type Coord, X -736.4729, Y 414.2327, Z 19.8907}; {point type Coord, X -744.4351, Y 414.2206, Z 17.9317}; {point type Coord, X -753.3527, Y 414.207, Z 17.044}; {point type Coord, X -763.2257, Y 414.192, Z 16.8664}; {point type Coord, X -775.4874, Y 414.1734, Z 16.6889}; {point type Coord, X -797.9407, Y 414.1392, Z 16.6889}; {point type Coord, X -811.7949, Y 414.1182, Z 16.8664}; {point type Coord, X -826.286, Y 414.0962, Z 17.044}; {point type Coord, X -846.518, Y 414.0654, Z 17.9317}), SymmetryMode false
  St3DCurveFeature37 "CATSt3DCurveFeatureName": Order 6, CreationType 2, ClosureMode false, ConstructionPoints ({point type OnCurve, Support St3DCurveFeature36, Real 0}; {point type Coord, X -736.2319, Y 414.2331, Z 28.2652}; {point type Coord, X -742.8135, Y 414.2231, Z 30.0575}; {point type Coord, X -749.5659, Y 414.2128, Z 31.071}; {point type Coord, X -757.8569, Y 414.2002, Z 31.9181}; {point type Coord, X -764.0111, Y 414.1908, Z 32.0221}; {point type Coord, X -772.986, Y 414.1772, Z 32.0633}; {point type Coord, X -797.3555, Y 414.1401, Z 31.3805}; {point type Coord, X -805.3901, Y 414.1279, Z 30.7013}; {point type Coord, X -814.4504, Y 414.1141, Z 29.1129}; {point type Coord, X -824.3655, Y 414.0991, Z 26.453}; {point type Coord, X -833.7677, Y 414.0848, Z 23.5311}; {point type OnCurve, Support St3DCurveFeature36, Real 1}), SymmetryMode false
  Line2: type PtPt, FirstPoint vertex of St3DCurveFeature35, SecondPoint vertex of St3DCurveFeature36
  Line3: type PtPt, FirstPoint vertex of St3DCurveFeature36, SecondPoint vertex of St3DCurveFeature35
  St3DCurveFeature38 "CATSt3DCurveFeatureName": Order 6, CreationType 2, ClosureMode false, ConstructionPoints ({point type OnCurve, Support St3DCurveFeature35, Real 0}; {point type Coord, X -877.1187, Y 161.7511, Z 12.9579}; {point type Coord, X -887.7723, Y 161.7715, Z 12.4885}; {point type Coord, X -899.4026, Y 161.7938, Z 13.3899}; {point type Coord, X -907.9469, Y 161.8102, Z 13.8861}; {point type Coord, X -937.067, Y 161.8661, Z 16.2919}; {point type Coord, X -956.0779, Y 161.9026, Z 17.6807}; {point type Coord, X -978.3768, Y 161.9454, Z 19.6925}; {point type Coord, X -999.5196, Y 161.9859, Z 21.1228}; {point type Coord, X -1033.7125, Y 162.0515, Z 23.3113}; {point type Coord, X -1053.7048, Y 162.0899, Z 24.0973}; {point type OnCurve, Support St3DCurveFeature35, Real 1}), SymmetryMode false
  Line4 "WING HELPER": type PtDir, RefPoint vertex of St3DCurveFeature35, Direction Line3, Start 173, End 0
  St3DCurveFeature39 "WING ROOT TOP": Order 6, CreationType 2, ClosureMode false, ConstructionPoints ({point type Coord, X -819.6632, Y 79.273, Z 0}; {point type Coord, X -835.2322, Y 75.5015, Z 5.8458}; {point type Coord, X -855.5458, Y 72.1419, Z 9.8544}; {point type Coord, X -879.9246, Y 69.4113, Z 11.8661}; {point type Coord, X -898.5691, Y 67.7691, Z 12.926}; {point type Coord, X -910.7505, Y 66.8316, Z 13.8477}; {point type Coord, X -934.7742, Y 64.7318, Z 15.5364}; {point type Coord, X -976.7629, Y 62.2425, Z 17.9007}; {point type Coord, X -1015.0037, Y 61.0054, Z 19.733}; {point type Coord, X -1087.8837, Y 58.013, Z 22.6291}; {point type Coord, X -1130.8396, Y 55.9263, Z 23.9801}; {point type Coord, X -1202.1401, Y 52.5398, Z 25.8129}), SymmetryMode false
  St3DCurveFeature40 "WING ROOT BOTT": Order 6, CreationType 2, ClosureMode false, ConstructionPoints ({point type Coord, X -819.6632, Y 79.273, Z 0}; {point type Coord, X -835.2322, Y 75.5015, Z -5.0214}; {point type Coord, X -855.5458, Y 72.1419, Z -5.4922}; {point type Coord, X -879.9246, Y 69.4113, Z -4.1128}; {point type Coord, X -898.5691, Y 67.7691, Z -2.868}; {point type Coord, X -910.7505, Y 66.8316, Z -1.7805}; {point type Coord, X -934.7742, Y 64.7318, Z 0.8708}; {point type Coord, X -976.7629, Y 62.2425, Z 6.7485}; {point type Coord, X -1015.0037, Y 61.0054, Z 12.1908}; {point type Coord, X -1087.8837, Y 58.013, Z 19.5923}; {point type Coord, X -1130.8396, Y 55.9263, Z 22.2046}; {point type OnCurve, Support St3DCurveFeature39, Real 1}), SymmetryMode false
  Line5: type PtPt, FirstPoint vertex of St3DCurveFeature35, SecondPoint vertex of St3DCurveFeature39
  Line6: type PtPt, FirstPoint vertex of St3DCurveFeature35, SecondPoint vertex of St3DCurveFeature39
  Loft6 "WINGS1": Sections (St3DCurveFeature37; St3DCurveFeature35), Guides (Line2; Line3)
  Loft7 "WINGS2": Sections (St3DCurveFeature36; St3DCurveFeature38), Guides (Line2; Line3)
  Loft8 "WINGS3": Sections (St3DCurveFeature38; St3DCurveFeature40), Guides (Line5; Line6)
  Loft9 "WINGS4": Sections (St3DCurveFeature35; St3DCurveFeature39), Guides (Line5; Line6)
  MultiSel6
  Line7: type PtDir, RefPoint vertex of St3DCurveFeature29, Direction xy-plane, Start 64, End 0
  StFrfSweepFeature1 "CATStFrfSweepFeatureName": Spine St3DCurveFeature29, SecondLimitPoint {point type OnCurve, Support St3DCurveFeature29, Real 1}, ProfileDeformation false, MaxOrderU 16, MaxOrderV 16, Profile Line7, FirstLimitPoint {point type OnCurve, Support St3DCurveFeature29, Real 0}
  Symmetry6: ToTransfor StFrfSweepFeature1, Reference zx-plane
  St3DCurveFeature41 "CATSt3DCurveFeatureName": Order 6, CreationType 2, ClosureMode false, ConstructionPoints ({point type OnCurve, Support St3DCurveFeature4, Real 1}; {point type Coord, X -989.4354, Y 3.253, Z 114.422}; {point type OnCurve, Support St3DCurveFeature5, Real 0.715625}), SymmetryMode false
  Symmetry7: ToTransfor St3DCurveFeature41, Reference zx-plane
  Join18: Elements (St3DCurveFeature41; Symmetry7)
  Join19 "9 SECTION TOP": Elements (St3DCurveFeature20; {symmetry ToTransfor St3DCurveFeature20, Reference zx-plane})
  Split3: ToCut Join19, Cutting St3DCurveFeature4
  Split4 "10 SECTION TOP": ToCut Split3, Cutting {symmetry ToTransfor St3DCurveFeature4, Reference zx-plane}
  Loft10: Sections (Split4; Join18), Guides (St3DCurveFeature4; {symmetry ToTransfor St3DCurveFeature4, Reference zx-plane})
  Sketch10 "ENGINE CENTER LINE" on zx-plane, origin (0, 0, 0), H (-1, 0, 0), V (0, 0, 1)
    line L1 (1390.9, 103.6793) -> (1390.9, 60.2293)
    point P1 (1390.9, 103.6793)
    point P2 (1390.9, 16.7793)
    line L2 (1390.9, 60.2293) -> (869.8, 60.2293)
    vertical: L1 V
    horizontal: L2 H
    fix: L1, P1, P2
  Sketch11 "ENGINE LINES" on zx-plane, origin (0, 0, 0), H (-1, 0, 0), V (0, 0, 1)
    line L1 (1313.864, 115.0437) -> (1313.864, 61.6363)
    point P2 (1313.864, 8.2289)
    line L2 (1148.15, 115.008) -> (1148.15, 53.3585)
    point P3 (1148.15, 115.008)
    point P4 (1148.15, -8.2911)
    line L3 (1124.3605, 114.409) -> (1124.3605, 51.8097)
    point P5 (1124.3605, 114.409)
    point P6 (1124.3605, -10.7896)
    line L4 (1094.8022, 113.8028) -> (1094.8022, 50.0541)
    point P7 (1094.8022, 113.8028)
    point P8 (1094.8022, -13.6947)
    line L5 (988.1404, 112.7474) -> (988.1404, 45.7582)
    point P9 (988.1404, 112.7474)
    point P10 (988.1404, -21.231)
    line L6 (889.9015, 108.511) -> (889.9015, 41.7899)
    point P11 (889.9015, 108.511)
    point P12 (889.9015, -24.9312)
    reference projected curve E1 from edge of St3DCurveFeature31
    reference projected curve E2 from edge of St3DCurveFeature31
    reference projected curve E3 from edge of St3DCurveFeature31
    reference projected curve E4 from edge of St3DCurveFeature31
    reference projected curve E5 from edge of St3DCurveFeature31
    reference projected point E6 (1313.864, 8.2289) from vertex of St3DCurveFeature31
    reference projected curve E7 from edge of St3DCurveFeature29
    reference projected curve E8 from edge of St3DCurveFeature29
    reference projected curve E9 from edge of St3DCurveFeature29
    reference projected curve E10 from edge of St3DCurveFeature29
    reference projected curve E11 from edge of St3DCurveFeature29
    point P13 (889.9015, 41.7899)
    line L7 (889.9015, 41.7899) -> (925.2049, 44.7417)
    point P19 (889.9015, 41.7899)
    line L8 (988.1404, 45.7582) -> (1003.4, 45.7582)
    line L9 (1094.8022, 50.0541) -> (1101.7, 50.0541)
    line L10 (1124.3605, 51.8097) -> (1132.9, 51.8097)
    line L11 (1148.15, 53.3585) -> (1161.3, 53.3585)
    line L12 (889.9015, 108.511) -> (935.4009, 112.3154)
    point P25 (935.4009, 112.3154)
    line L13 (889.9015, 108.511) -> (878.8214, 107.5845)
    line L14 (884.3615, 108.0478) -> (889.9015, 41.7899)
    point P27 (884.3615, 108.0478)
    line L15 (1313.864, 61.6363) -> (1331.1, 61.6363)
    vertical: L1 V, L2 V, L3 V, L4 V, L6 V, L5 V
    coincidence: P12 E1, P10 E2, P8 E3, P6 E4, P4 E5, P2 E6, P3 E7, P5 E8, P7 E9, P9 E10, P11 E11, P19 P13
    horizontal: L8 H, L9 H, L10 H, L11 H, L15 H
    fix: P19, L12, P25
    parallelism: L13 L12, L7 L12
    midpoint: P27 L13
    perpendicularity: L14 L13
  Circle1: type CenterAxis, Start 0, End 180, Pt Sketch11.P19, Axis Sketch11.L7, Radius 66.489
  Circle2: type CenterAxis, Start 0, End 180, Pt vertex [element of Sketch11 | element of Sketch11], Axis {line type PtDir, RefPoint vertex [element of Sketch11 | element of Sketch11], Direction yz-plane, Start 43, End 0}, Radius 66.989
  Circle3: type CenterAxis, Start 0, End 180, Pt vertex [element of Sketch11 | element of Sketch11], Axis {line type PtDir, RefPoint vertex [element of Sketch11 | element of Sketch11], Direction yz-plane, Start 43, End 0}, Radius 63.749
  Circle4: type CenterAxis, Start 0, End 180, Pt vertex [element of Sketch11 | element of Sketch11], Axis {line type PtDir, RefPoint vertex [element of Sketch11 | element of Sketch11], Direction yz-plane, Start 43, End 0}, Radius 62.599
  Circle5: type CenterAxis, Start 0, End 180, Pt vertex [element of Sketch11 | element of Sketch11], Axis {line type PtDir, RefPoint vertex [element of Sketch11 | element of Sketch11], Direction yz-plane, Start 43, End 0}, Radius 61.65
  Circle6: type CenterAxis, Start 0, End 180, Pt vertex [element of Sketch11 | element of Sketch11], Axis {line type PtDir, RefPoint vertex [element of Sketch11 | element of Sketch11], Direction yz-plane, Start 43, End 0}, Radius 53.407
  Circle7: type CenterAxis, Start 0, End 180, Pt vertex [element of Sketch10 | element of Sketch10], Axis {line type PtDir, RefPoint vertex [element of Sketch10 | element of Sketch10], Direction yz-plane, Start 43, End 0}, Radius 43.45
  Loft11: Sections (Circle1; Circle2; Circle3; Circle4; Circle5; Circle6; Circle7)
  Fill2: Boundary Circle6
  Point12: (0, 0, 0), relative to vertex of St3DCurveFeature7
  Line8: type PtDir, RefPoint Point12, Direction xy-plane, Start 54, End 0
  Plane4: type Normal, Curve Line8, RefPoint Point12
  St3DCurveFeature42 "CATSt3DCurveFeatureName": Order 6, CreationType 2, ClosureMode false, ConstructionPoints ({point type Coord, X -525.9686, Y 48.6848, Z 10.1129}; {point type Coord, X -554.8334, Y 48.5989, Z 24.2845}; {point type Coord, X -574.6075, Y 48.8568, Z 30.5291}; {point type Coord, X -600.7983, Y 48.8031, Z 35.9815}; {point type Coord, X -627.382, Y 48.5369, Z 42.2193}; {point type Coord, X -663.6311, Y 47.4997, Z 65.4783}; {point type Coord, X -713.6192, Y 44.7367, Z 84.099}; {point type Coord, X -738.7649, Y 42.8206, Z 91.8255}; {point type Coord, X -775.555, Y 39.6916, Z 100.2913}; {point type Coord, X -818.3837, Y 36.4201, Z 104.6396}), SymmetryMode false
  St3DCurveFeature43 "CATSt3DCurveFeatureName": Order 6, CreationType 2, ClosureMode false, ConstructionPoints ({point type Coord, X -525.9838, Y 55.3979, Z 9.8013}; {point type Coord, X -543.2538, Y 55.9968, Z 19.3513}; {point type Coord, X -574.5548, Y 56.772, Z 30.9118}; {point type Coord, X -628.0893, Y 57.7, Z 42.221}; {point type Coord, X -661.1129, Y 56.9586, Z 63.8342}; {point type Coord, X -721.9703, Y 52.2509, Z 86.4526}; {point type Coord, X -755.0441, Y 48.0325, Z 96.0026}; {point type Coord, X -785.2518, Y 44.2786, Z 101.1624}; {point type Coord, X -818.4157, Y 38.7854, Z 104.4124}), SymmetryMode false
  St3DCurveFeature44 "CATSt3DCurveFeatureName": Order 6, CreationType 2, ClosureMode false, ConstructionPoints ({point type OnCurve, Support St3DCurveFeature42, Real 0}; {point type OnCurve, Support St3DCurveFeature43, Real 0}), SymmetryMode false
  StFrfSweepFeature2 "CATStFrfSweepFeatureName": Guide St3DCurveFeature43, Spine St3DCurveFeature42, SecondLimitPoint {point type OnCurve, Support St3DCurveFeature42, Real 1}, ProfileDeformation false, MaxOrderU 16, MaxOrderV 16, Profile St3DCurveFeature44, FirstLimitPoint {point type OnCurve, Support St3DCurveFeature42, Real 0}
  Symmetry8: ToTransfor StFrfSweepFeature2, Reference zx-plane
  St3DCurveFeature45 "CATSt3DCurveFeatureName": Order 6, CreationType 2, ClosureMode false, ConstructionPoints ({point type OnCurve, Support St3DCurveFeature42, Real 1}; {point type OnCurve, Support Split4, Real 0}), SymmetryMode false
  StFrfSweepFeature3 "CATStFrfSweepFeatureName": Spine St3DCurveFeature42, SecondLimitPoint {point type OnCurve, Support St3DCurveFeature42, Real 1}, ProfileDeformation false, MaxOrderU 16, MaxOrderV 16, Profile St3DCurveFeature45, FirstLimitPoint {point type OnCurve, Support St3DCurveFeature42, Real 0}
  Project1 "CRAZY INTERSURFACE": ToProject St3DCurveFeature42, Support Loft3, Direction (0, 1, 0)
  St3DCurveFeature46 "CATSt3DCurveFeatureName": Order 6, CreationType 2, ClosureMode false, ConstructionPoints ({point type OnCurve, Support Project1, Real 0}; {point type OnCurve, Support St3DCurveFeature43, Real 0}), SymmetryMode false
  St3DCurveFeature47 "CATSt3DCurveFeatureName": Order 6, CreationType 2, ClosureMode false, ConstructionPoints ({point type OnCurve, Support Project1, Real 1}; {point type OnCurve, Support St3DCurveFeature43, Real 1}), SymmetryMode false
  Loft12 "NOZZLE BODY INTEFACE1": Sections (St3DCurveFeature46; St3DCurveFeature47), Guides (Project1; St3DCurveFeature43)
  Project2: ToProject St3DCurveFeature43, Support StFrfSweepFeature1, Direction (0, 1, 0)
  St3DCurveFeature48 "CATSt3DCurveFeatureName": Order 6, CreationType 2, ClosureMode false, ConstructionPoints ({point type OnCurve, Support St3DCurveFeature43, Real 0}; {point type OnCurve, Support Project2, Real 0}), SymmetryMode false
  St3DCurveFeature49 "CATSt3DCurveFeatureName": Order 6, CreationType 2, ClosureMode false, ConstructionPoints ({point type OnCurve, Support Project2, Real 1}; {point type OnCurve, Support St3DCurveFeature43, Real 1}), SymmetryMode false
  Loft13 "NOZZLE BODY INTERFACE 2": Sections (St3DCurveFeature48; St3DCurveFeature49), Guides (St3DCurveFeature43; Project2)
  MultiSel7
  St3DCurveFeature50 "CATSt3DCurveFeatureName": Order 6, CreationType 2, ClosureMode false, ConstructionPoints ({point type OnCurve, Support St3DCurveFeature4, Real 1}; {point type Coord, X -990.0525, Y 17.5033, Z 112.2858}; {point type Coord, X -990.8247, Y 24.5659, Z 111.886}; {point type OnCurve, Support St3DCurveFeature34, Real 0}), SymmetryMode false
  Join20: Elements (St3DCurveFeature47; St3DCurveFeature49)
  St3DCurveFeature51 "CATSt3DCurveFeatureName": Order 6, CreationType 2, ClosureMode false, ConstructionPoints ({point type OnCurve, Support Project2, Real 1}; {point type Coord, X -823.3395, Y 43.2907, Z 104.8785}; {point type Coord, X -830.5341, Y 42.2987, Z 105.3147}; {point type Coord, X -839.0855, Y 41.2145, Z 105.8285}; {point type Coord, X -851.6704, Y 39.6587, Z 106.6197}; {point type Coord, X -857.9809, Y 38.9223, Z 107.1396}; {point type Coord, X -872.7551, Y 37.1231, Z 107.7747}; {point type Coord, X -879.3784, Y 36.3583, Z 108.0763}; {point type Coord, X -893.1956, Y 34.857, Z 108.6442}; {point type Coord, X -907.5093, Y 33.3778, Z 109.1554}; {point type Coord, X -932.2495, Y 31.6688, Z 110.2913}; {point type Coord, X -945.3229, Y 31.2886, Z 110.9161}; {point type Coord, X -965.4308, Y 30.7601, Z 111.8816}; {point type Coord, X -980.8454, Y 30.6497, Z 112.4496}; {point type Coord, X -988.2018, Y 30.6594, Z 112.6768}; {point type OnCurve, Support St3DCurveFeature34, Real 0}), SymmetryMode false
